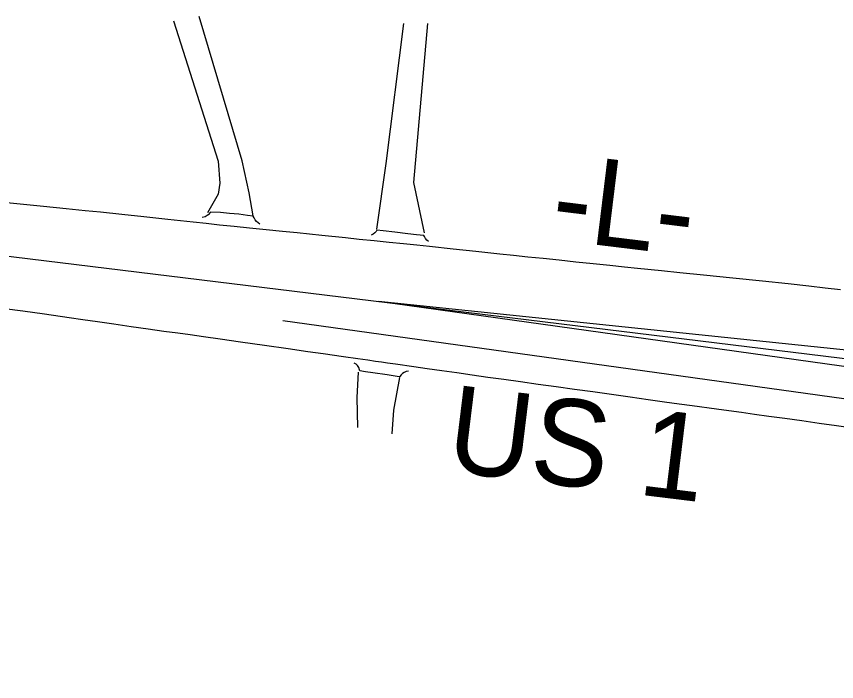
# Model space of a CAD drawing. Extents: x 1756435 to 1766932, y 416863 to 426859.
# Drawn here: x 1761555.4 to 1761886.1, y 423824.4 to 424092.6 of the extents above; entities that cross this region are included whole.
import ezdxf

# ---------------------------------------------------------------- set-up
doc = ezdxf.new("R2010")
doc.units = 0
for name, color, linetype in [('Exist Roads EOP', 7, 'Continuous'), ('Exist Roads EOP Other', 7, 'Continuous'), ('Exist Roads Soil', 7, 'Continuous'), ('Prop Horizontal Alignment', 7, 'Continuous'), ('Prop Lane Lines', 7, 'Continuous'), ('Prop Shade Light', 7, 'Continuous'), ('Sheet Data Field CELL', 7, 'Continuous')]:
    doc.layers.add(name, color=color, linetype=linetype)

msp = doc.modelspace()

# ---------------------------------------------------------------- linework, layer by layer
at = {"layer": 'Exist Roads EOP'}
for points in [[(1761887.69, 423982.4), (1761881.56, 423983.08), (1761874.94, 423983.82), (1761866.52, 423984.73), (1761856.3, 423985.81), (1761844.28, 423987.06), (1761832.46, 423988.28), (1761822.85, 423989.27), (1761815.47, 423990.02), (1761805.87, 423991), (1761800.67, 423991.53), (1761794.71, 423992.14), (1761787.98, 423992.84), (1761781.01, 423993.56), (1761774.31, 423994.26), (1761767.86, 423994.93), (1761761.69, 423995.58), (1761755.84, 423996.21), (1761750.39, 423996.79), (1761740.67, 423997.82), (1761731.53, 423998.79), (1761721.98, 423999.78), (1761716.92, 424000.31), (1761711.52, 424000.86), (1761705.77, 424001.46), (1761699.68, 424002.09), (1761693.66, 424002.71), (1761688.12, 424003.28), (1761678.52, 424004.26), (1761668.61, 424005.28), (1761662.69, 424005.88), (1761656.14, 424006.54), (1761649.47, 424007.22), (1761643.2, 424007.87), (1761637.35, 424008.48), (1761631.9, 424009.06), (1761626.7, 424009.62), (1761621.58, 424010.18), (1761616.54, 424010.74), (1761606.8, 424011.82), (1761597.98, 424012.77), (1761589.3, 424013.66), (1761583.15, 424014.28), (1761575.5, 424015.05), (1761566.35, 424015.98), (1761557.01, 424016.92), (1761548.77, 424017.76)], [(1761550.64, 423974.88), (1761558.06, 423973.85), (1761566.79, 423972.62), (1761576.68, 423971.19), (1761582.17, 423970.4), (1761588.16, 423969.53), (1761594.66, 423968.6), (1761601.65, 423967.6), (1761608.58, 423966.62), (1761614.85, 423965.74), (1761620.48, 423964.96), (1761625.46, 423964.29), (1761630.83, 423963.55), (1761637.61, 423962.6), (1761645.82, 423961.43), (1761655.45, 423960.04), (1761664.98, 423958.66), (1761672.87, 423957.52), (1761679.15, 423956.62), (1761687.38, 423955.43), (1761693.13, 423954.63), (1761697.1, 423954.09), (1761700.18, 423953.66), (1761702.62, 423953.3), (1761705.12, 423952.93), (1761708.34, 423952.47), (1761715.62, 423951.44), (1761720.99, 423950.67), (1761726.98, 423949.82), (1761733.06, 423948.96), (1761739.25, 423948.08), (1761745.53, 423947.19), (1761751.99, 423946.28), (1761758.72, 423945.34), (1761765.73, 423944.37), (1761773, 423943.37), (1761780.43, 423942.35), (1761787.89, 423941.31), (1761795.39, 423940.26), (1761802.92, 423939.2), (1761810.14, 423938.18), (1761816.7, 423937.26), (1761822.61, 423936.45), (1761827.86, 423935.74), (1761837.75, 423934.41), (1761842.73, 423933.72), (1761847.74, 423933.02), (1761853.03, 423932.28), (1761858.85, 423931.46), (1761865.19, 423930.58), (1761872.07, 423929.62), (1761879.13, 423928.63), (1761886.03, 423927.67), (1761892.76, 423926.72)]]:
    msp.add_lwpolyline(points, dxfattribs=at)
at = {"layer": 'Exist Roads EOP Other'}
for points in [[(1761650.95, 424012.21), (1761649.23, 424021.45), (1761646.45, 424034.32), (1761629.08, 424092.62)], [(1761618.82, 424090.77), (1761636.74, 424034.28), (1761637.41, 424025.31), (1761636.77, 424020.91), (1761632.44, 424013.41)], [(1761653.65, 424008.84), (1761652.9, 424009.32), (1761652.23, 424009.87), (1761651.71, 424010.54), (1761651.32, 424011.33), (1761650.86, 424012.05), (1761648.56, 424012.36), (1761645.08, 424012.81), (1761641.39, 424013.13), (1761637.74, 424013.5), (1761633.67, 424013.73), (1761632.71, 424012.6), (1761631.5, 424011.77), (1761630.35, 424011.48)], [(1761721.53, 424001.79), (1761720.95, 424002.41), (1761720.39, 424003.07), (1761719.97, 424003.86), (1761719.75, 424004.24), (1761716.78, 424004.54), (1761713.25, 424004.92), (1761707.97, 424005.57), (1761703.27, 424006.14), (1761700.7, 424006.41), (1761700.44, 424005.94), (1761699.93, 424005.28), (1761699.29, 424004.76), (1761698.5, 424004.42)], [(1761713.47, 423949.56), (1761712.52, 423949.39), (1761711.76, 423949.06), (1761711.11, 423948.59), (1761710.55, 423948.04), (1761710.08, 423947.43), (1761709.77, 423947.29), (1761704.96, 423948.02), (1761699.12, 423948.9), (1761696.21, 423949.35), (1761693.86, 423949.71), (1761693.71, 423950.09), (1761693.48, 423951.04), (1761693, 423951.79), (1761692.42, 423952.44), (1761691.58, 423952.81)]]:
    msp.add_lwpolyline(points, dxfattribs=at)
at = {"layer": 'Exist Roads Soil'}
for points in [[(1761711.54, 424089.7), (1761704.41, 424033.36), (1761700.58, 424006.89)], [(1761720, 424005.33), (1761715.69, 424025.58), (1761721.35, 424089.71)], [(1761693.19, 423949.16), (1761692.66, 423939.01), (1761692.91, 423926.81)], [(1761706.89, 423924.27), (1761707.66, 423933.9), (1761709.97, 423946.99)]]:
    msp.add_lwpolyline(points, dxfattribs=at)
at = {"layer": 'Prop Horizontal Alignment'}
msp.add_line((1760837.84, 424083.41), (1762954.58, 423824.38), dxfattribs=at)
at = {"layer": 'Prop Lane Lines'}
for p, q in [((1761701.4, 423977.73), (1761997.58, 423936.5)), ((1761701.4, 423977.73), (1762029.68, 423943.61)), ((1761662.86, 423969.97), (1762058.2, 423914.93))]:
    msp.add_line(p, q, dxfattribs=at)
at = {"layer": 'Prop Shade Light'}
for points in [[(1761887.69, 423982.4), (1761881.56, 423983.08), (1761874.94, 423983.82), (1761866.52, 423984.73), (1761856.3, 423985.81), (1761844.28, 423987.06), (1761832.46, 423988.28), (1761822.85, 423989.27), (1761815.47, 423990.02), (1761805.87, 423991), (1761800.67, 423991.53), (1761794.71, 423992.14), (1761787.98, 423992.84), (1761781.01, 423993.56), (1761774.31, 423994.26), (1761767.86, 423994.93), (1761761.69, 423995.58), (1761755.84, 423996.21), (1761750.39, 423996.79), (1761740.67, 423997.82), (1761731.53, 423998.79), (1761721.98, 423999.78), (1761716.92, 424000.31), (1761711.52, 424000.86), (1761705.77, 424001.46), (1761699.68, 424002.09), (1761693.66, 424002.71), (1761688.12, 424003.28), (1761678.52, 424004.26), (1761668.61, 424005.28), (1761662.69, 424005.88), (1761656.14, 424006.54), (1761649.47, 424007.22), (1761643.2, 424007.87), (1761637.35, 424008.48), (1761631.9, 424009.06), (1761626.7, 424009.62), (1761621.58, 424010.18), (1761616.54, 424010.74), (1761606.8, 424011.82), (1761597.98, 424012.77), (1761589.3, 424013.66), (1761583.15, 424014.28), (1761575.5, 424015.05), (1761566.35, 424015.98), (1761557.01, 424016.92), (1761548.77, 424017.76)], [(1761550.64, 423974.88), (1761558.06, 423973.85), (1761566.79, 423972.62), (1761576.68, 423971.19), (1761582.17, 423970.4), (1761588.16, 423969.53), (1761594.66, 423968.6), (1761601.65, 423967.6), (1761608.58, 423966.62), (1761614.85, 423965.74), (1761620.48, 423964.96), (1761625.46, 423964.29), (1761630.83, 423963.55), (1761637.61, 423962.6), (1761645.82, 423961.43), (1761655.45, 423960.04), (1761664.98, 423958.66), (1761672.87, 423957.52), (1761679.15, 423956.62), (1761687.38, 423955.43), (1761693.13, 423954.63), (1761697.1, 423954.09), (1761700.18, 423953.66), (1761702.62, 423953.3), (1761705.12, 423952.93), (1761708.34, 423952.47), (1761715.62, 423951.44), (1761720.99, 423950.67), (1761726.98, 423949.82), (1761733.06, 423948.96), (1761739.25, 423948.08), (1761745.53, 423947.19), (1761751.99, 423946.28), (1761758.72, 423945.34), (1761765.73, 423944.37), (1761773, 423943.37), (1761780.43, 423942.35), (1761787.89, 423941.31), (1761795.39, 423940.26), (1761802.92, 423939.2), (1761810.14, 423938.18), (1761816.7, 423937.26), (1761822.61, 423936.45), (1761827.86, 423935.74), (1761837.75, 423934.41), (1761842.73, 423933.72), (1761847.74, 423933.02), (1761853.03, 423932.28), (1761858.85, 423931.46), (1761865.19, 423930.58), (1761872.07, 423929.62), (1761879.13, 423928.63), (1761886.03, 423927.67), (1761892.76, 423926.72)]]:
    msp.add_lwpolyline(points, dxfattribs=at)

# ---------------------------------------------------------------- texts
at = {"layer": 'Sheet Data Field CELL'}
for s, p in [('-L-', (1761770.18, 424002.87)), ('US 1', (1761727.97, 423909.37))]:
    msp.add_text(s, height=35, rotation=353.0234, dxfattribs=at).set_placement(p)

doc.saveas('drawing.dxf')
